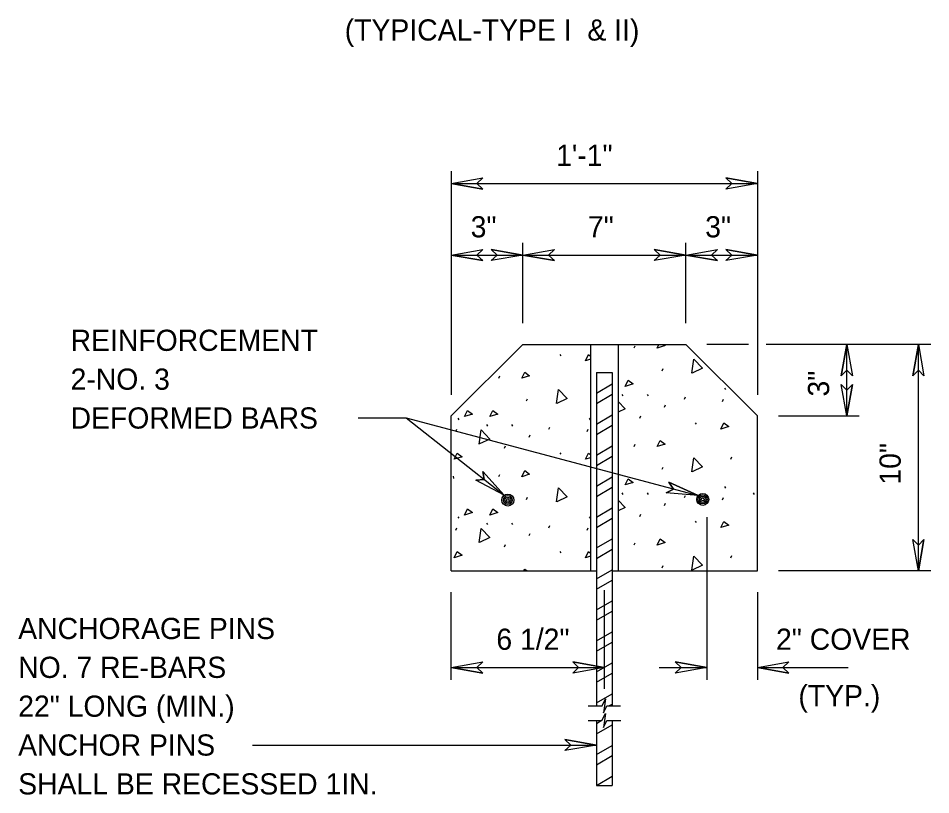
# Model space of a CAD drawing. Extents: x 12.4 to 19.6, y 6 to 16.2.
# Drawn here: x 16.834 to 19.416, y 11.739 to 13.937 of the extents above; entities that cross this region are included whole.
import ezdxf

# ---------------------------------------------------------------- set-up
doc = ezdxf.new("R2010")
doc.units = 0
for name, color, linetype in [('DETL-DIMS', 7, 'Continuous'), ('DETL-LINE', 7, 'Continuous'), ('DETL-NOTE', 7, 'Continuous'), ('DETL-PATT', 7, 'Continuous')]:
    doc.layers.add(name, color=color, linetype=linetype)

msp = doc.modelspace()

# ---------------------------------------------------------------- linework, layer by layer
at = {"layer": 'DETL-DIMS'}
for p, q in [((18.0593, 13.5044), (18.0593, 12.8713)), ((18.9255, 13.5044), (18.9255, 12.8713)), ((18.0593, 13.4694), (18.1486, 13.4851)), ((18.1318, 13.4694), (18.1486, 13.4851)), ((18.9255, 13.4694), (18.8361, 13.4851)), ((18.8361, 13.4851), (18.853, 13.4694)), ((18.0593, 13.4694), (18.9255, 13.4694)), ((18.0593, 13.4694), (18.1486, 13.4536)), ((18.1486, 13.4536), (18.1318, 13.4694)), ((18.9255, 13.4694), (18.8361, 13.4536)), ((18.853, 13.4694), (18.8361, 13.4536)), ((18.2618, 13.0738), (18.2618, 13.3019)), ((18.723, 13.0738), (18.723, 13.3019)), ((18.0593, 13.2669), (18.1486, 13.2826)), ((18.1318, 13.2669), (18.1486, 13.2826)), ((18.2618, 13.2669), (18.1724, 13.2826)), ((18.1724, 13.2826), (18.1893, 13.2669)), ((18.2618, 13.2669), (18.3511, 13.2826)), ((18.3343, 13.2669), (18.3511, 13.2826)), ((18.723, 13.2669), (18.6336, 13.2826)), ((18.6336, 13.2826), (18.6505, 13.2669)), ((18.723, 13.2669), (18.8124, 13.2826)), ((18.7955, 13.2669), (18.8124, 13.2826)), ((18.9255, 13.2669), (18.8361, 13.2826)), ((18.8361, 13.2826), (18.853, 13.2669)), ((18.0593, 13.2669), (18.2618, 13.2669)), ((18.0593, 13.2669), (18.1486, 13.2511)), ((18.1486, 13.2511), (18.1318, 13.2669)), ((18.2618, 13.2669), (18.1724, 13.2511)), ((18.1893, 13.2669), (18.1724, 13.2511)), ((18.2618, 13.2669), (18.723, 13.2669)), ((18.2618, 13.2669), (18.3511, 13.2511)), ((18.3511, 13.2511), (18.3343, 13.2669)), ((18.723, 13.2669), (18.6336, 13.2511)), ((18.6505, 13.2669), (18.6336, 13.2511)), ((18.723, 13.2669), (18.9255, 13.2669)), ((18.723, 13.2669), (18.8124, 13.2511)), ((18.8124, 13.2511), (18.7955, 13.2669)), ((18.9255, 13.2669), (18.8361, 13.2511)), ((18.853, 13.2669), (18.8361, 13.2511)), ((18.9005, 13.0138), (18.783, 13.0138)), ((19.4161, 13.0138), (18.9505, 13.0138)), ((19.1786, 13.0138), (19.1629, 12.9244)), ((19.1786, 12.8113), (19.1786, 13.0138)), ((19.1786, 13.0138), (19.1944, 12.9244)), ((19.3811, 13.0138), (19.3654, 12.9244)), ((19.3811, 12.3725), (19.3811, 13.0138)), ((19.3811, 13.0138), (19.3969, 12.9244)), ((19.1629, 12.9244), (19.1786, 12.9413)), ((19.1786, 12.9413), (19.1944, 12.9244)), ((19.3654, 12.9244), (19.3811, 12.9413)), ((19.3811, 12.9413), (19.3969, 12.9244)), ((19.1786, 12.8113), (19.1629, 12.9006)), ((19.1786, 12.8838), (19.1629, 12.9006)), ((19.1786, 12.8113), (19.1944, 12.9006)), ((19.1944, 12.9006), (19.1786, 12.8838)), ((18.9855, 12.8113), (19.2136, 12.8113)), ((17.796, 12.8055), (17.9316, 12.8055)), ((17.9316, 12.8055), (18.2094, 12.5866)), ((17.9316, 12.8055), (18.7579, 12.5858)), ((18.2094, 12.5866), (18.1489, 12.6544)), ((18.1489, 12.6544), (18.1524, 12.6315)), ((18.1524, 12.6315), (18.1294, 12.6296)), ((18.2094, 12.5866), (18.1294, 12.6296)), ((18.6878, 12.6044), (18.6675, 12.5935)), ((18.7579, 12.5858), (18.6755, 12.624)), ((18.6755, 12.624), (18.6878, 12.6044)), ((18.7579, 12.5858), (18.6675, 12.5935)), ((18.7824, 12.5249), (18.7824, 12.0641)), ((19.3811, 12.3725), (19.3654, 12.4619)), ((19.3811, 12.445), (19.3654, 12.4619)), ((19.3811, 12.3725), (19.3969, 12.4619)), ((19.3969, 12.4619), (19.3811, 12.445)), ((19.4161, 12.3725), (18.9855, 12.3725)), ((18.4924, 12.3175), (18.4924, 12.0383)), ((18.0593, 12.0641), (18.0593, 12.3125)), ((18.9255, 12.3125), (18.9255, 12.0641)), ((18.0593, 12.0991), (18.1486, 12.1149)), ((18.1318, 12.0991), (18.1486, 12.1149)), ((18.4924, 12.0991), (18.403, 12.1149)), ((18.403, 12.1149), (18.4199, 12.0991)), ((18.7824, 12.0991), (18.693, 12.1149)), ((18.693, 12.1149), (18.7099, 12.0991)), ((18.9255, 12.0991), (19.0149, 12.1149)), ((18.998, 12.0991), (19.0149, 12.1149)), ((18.0593, 12.0991), (18.4924, 12.0991)), ((18.0593, 12.0991), (18.1486, 12.0834)), ((18.1486, 12.0834), (18.1318, 12.0991)), ((18.4924, 12.0991), (18.403, 12.0834)), ((18.4199, 12.0991), (18.403, 12.0834)), ((18.6474, 12.0991), (18.7824, 12.0991)), ((18.7824, 12.0991), (18.693, 12.0834)), ((18.7099, 12.0991), (18.693, 12.0834)), ((18.9255, 12.0991), (19.1828, 12.0991)), ((18.9255, 12.0991), (19.0149, 12.0834)), ((19.0149, 12.0834), (18.998, 12.0991)), ((17.4969, 11.8795), (18.4699, 11.8795)), ((18.4699, 11.8795), (18.3805, 11.8953)), ((18.3805, 11.8953), (18.3974, 11.8795)), ((18.4699, 11.8795), (18.3805, 11.8638)), ((18.3974, 11.8795), (18.3805, 11.8638))]:
    msp.add_line(p, q, dxfattribs=at)
for points in [[(18.1486, 13.4536), (18.0593, 13.4694), (18.1486, 13.4851), (18.1318, 13.4694)], [(18.8361, 13.4851), (18.9255, 13.4694), (18.8361, 13.4536), (18.853, 13.4694)], [(18.1486, 13.2511), (18.0593, 13.2669), (18.1486, 13.2826), (18.1318, 13.2669)], [(18.1724, 13.2826), (18.2618, 13.2669), (18.1724, 13.2511), (18.1893, 13.2669)], [(18.3511, 13.2511), (18.2618, 13.2669), (18.3511, 13.2826), (18.3343, 13.2669)], [(18.6336, 13.2826), (18.723, 13.2669), (18.6336, 13.2511), (18.6505, 13.2669)], [(18.8124, 13.2511), (18.723, 13.2669), (18.8124, 13.2826), (18.7955, 13.2669)], [(18.8361, 13.2826), (18.9255, 13.2669), (18.8361, 13.2511), (18.853, 13.2669)], [(19.1629, 12.9244), (19.1786, 13.0138), (19.1944, 12.9244), (19.1786, 12.9413)], [(19.3654, 12.9244), (19.3811, 13.0138), (19.3969, 12.9244), (19.3811, 12.9413)], [(19.1944, 12.9006), (19.1786, 12.8113), (19.1629, 12.9006), (19.1786, 12.8838)], [(18.1489, 12.6544), (18.2094, 12.5866), (18.1294, 12.6296), (18.1524, 12.6315)], [(18.6755, 12.624), (18.7579, 12.5858), (18.6675, 12.5935), (18.6878, 12.6044)], [(19.3969, 12.4619), (19.3811, 12.3725), (19.3654, 12.4619), (19.3811, 12.445)], [(18.1486, 12.0834), (18.0593, 12.0991), (18.1486, 12.1149), (18.1318, 12.0991)], [(18.403, 12.1149), (18.4924, 12.0991), (18.403, 12.0834), (18.4199, 12.0991)], [(18.693, 12.1149), (18.7824, 12.0991), (18.693, 12.0834), (18.7099, 12.0991)], [(19.0149, 12.0834), (18.9255, 12.0991), (19.0149, 12.1149), (18.998, 12.0991)], [(18.3805, 11.8953), (18.4699, 11.8795), (18.3805, 11.8638), (18.3974, 11.8795)]]:
    msp.add_lwpolyline(points, close=True, dxfattribs=at)
at = {"layer": 'DETL-LINE'}
for p, q in [((18.0593, 12.8113), (18.2618, 13.0138)), ((18.2618, 13.0138), (18.723, 13.0138)), ((18.453, 13.0138), (18.453, 12.3725)), ((18.5318, 13.0138), (18.5318, 12.3725)), ((18.723, 13.0138), (18.9255, 12.8113)), ((18.4699, 12.9343), (18.4699, 11.99)), ((18.4699, 12.9343), (18.5149, 12.9343)), ((18.5149, 12.9343), (18.5149, 11.99)), ((18.0593, 12.3725), (18.0593, 12.8113)), ((18.9255, 12.3725), (18.9255, 12.8113)), ((18.0593, 12.3725), (18.4699, 12.3725)), ((18.5149, 12.3725), (18.9255, 12.3725)), ((18.4465, 11.99), (18.486, 11.99)), ((18.4999, 11.99), (18.5381, 11.99)), ((18.447, 11.9485), (18.4855, 11.9485)), ((18.4699, 11.9485), (18.4699, 11.765)), ((18.4994, 11.9485), (18.5388, 11.9485)), ((18.5149, 11.9485), (18.5149, 11.765)), ((18.4699, 11.765), (18.5149, 11.765))]:
    msp.add_line(p, q, dxfattribs=at)
for points in [[(18.486, 11.99), (18.496, 12.0106), (18.4906, 11.9704), (18.4999, 11.99)], [(18.4855, 11.9485), (18.4955, 11.969), (18.4901, 11.9289), (18.4994, 11.9485)]]:
    msp.add_lwpolyline(points, dxfattribs=at)
for centre, radius in [((18.2195, 12.573), 0.0169), ((18.2195, 12.573), 0.0127), ((18.2195, 12.573), 0.00844), ((18.2195, 12.573), 0.00422), ((18.7709, 12.575), 0.0169), ((18.7709, 12.575), 0.0127), ((18.7709, 12.575), 0.00844), ((18.7709, 12.575), 0.00422)]:
    msp.add_circle(centre, radius, dxfattribs=at)
at = {"layer": 'DETL-PATT'}
for p, q in [((18.5771, 13.004), (18.5799, 13.0102)), ((18.3663, 12.9857), (18.3691, 12.9815)), ((18.6559, 12.9393), (18.6587, 12.9455)), ((18.1939, 12.9186), (18.1966, 12.9248)), ((18.4699, 12.8758), (18.5149, 12.9018)), ((18.8325, 12.89), (18.8353, 12.8859)), ((18.2726, 12.8539), (18.2754, 12.8601)), ((18.4699, 12.8465), (18.5149, 12.8725)), ((18.5421, 12.8724), (18.5449, 12.8682)), ((18.6135, 12.8724), (18.6162, 12.8682)), ((18.719, 12.8588), (18.7218, 12.865)), ((18.8272, 12.8526), (18.83, 12.8588)), ((18.6628, 12.8366), (18.6656, 12.8428)), ((18.4699, 12.788), (18.5149, 12.8141)), ((18.5934, 12.8053), (18.5961, 12.8116)), ((18.0779, 12.8046), (18.0807, 12.8005)), ((18.1589, 12.787), (18.1616, 12.7828)), ((18.2302, 12.787), (18.233, 12.7828)), ((18.4493, 12.8046), (18.452, 12.8005)), ((18.4699, 12.7588), (18.5149, 12.7849)), ((18.7495, 12.7922), (18.7523, 12.788)), ((18.0727, 12.7672), (18.0754, 12.7734)), ((18.2796, 12.7512), (18.2824, 12.7574)), ((18.3358, 12.7734), (18.3386, 12.7796)), ((18.444, 12.7672), (18.4468, 12.7734)), ((18.5771, 12.7251), (18.5799, 12.7313)), ((18.2101, 12.7199), (18.2129, 12.7262)), ((18.3663, 12.7068), (18.3691, 12.7026)), ((18.4699, 12.7004), (18.5149, 12.7264)), ((18.4699, 12.6711), (18.5149, 12.6971)), ((18.8504, 12.6888), (18.8532, 12.6951)), ((18.6559, 12.6604), (18.6587, 12.6666)), ((18.0651, 12.6403), (18.0658, 12.634)), ((18.1939, 12.6397), (18.1966, 12.6459)), ((18.4699, 12.6128), (18.5149, 12.6386)), ((18.4699, 12.5835), (18.5149, 12.6095)), ((18.8325, 12.6112), (18.8353, 12.607)), ((18.2726, 12.575), (18.2754, 12.5812)), ((18.5421, 12.5935), (18.5449, 12.5893)), ((18.6135, 12.5935), (18.6162, 12.5893)), ((18.719, 12.5799), (18.7218, 12.5862)), ((18.8272, 12.5737), (18.83, 12.5799)), ((18.9135, 12.5935), (18.9162, 12.5893)), ((18.4699, 12.525), (18.5149, 12.551)), ((18.6628, 12.5577), (18.6656, 12.564)), ((18.0779, 12.5258), (18.0807, 12.5216)), ((18.4493, 12.5258), (18.452, 12.5216)), ((18.5934, 12.5265), (18.5961, 12.5327)), ((18.1589, 12.5081), (18.1616, 12.5039)), ((18.2302, 12.5081), (18.233, 12.5039)), ((18.3358, 12.4945), (18.3386, 12.5008)), ((18.4699, 12.4958), (18.5149, 12.5218)), ((18.7495, 12.5133), (18.7523, 12.5092)), ((18.0727, 12.4883), (18.0754, 12.4945)), ((18.2796, 12.4723), (18.2824, 12.4786)), ((18.444, 12.4883), (18.4468, 12.4945)), ((18.2101, 12.4411), (18.2129, 12.4473)), ((18.4699, 12.4374), (18.5149, 12.4633)), ((18.5771, 12.4462), (18.5799, 12.4524)), ((18.3663, 12.4279), (18.3691, 12.4238)), ((18.4699, 12.4081), (18.5149, 12.4341)), ((18.8504, 12.4099), (18.8532, 12.4162)), ((18.4699, 12.3496), (18.5149, 12.3756)), ((18.6559, 12.3815), (18.6587, 12.3878)), ((18.4699, 12.3204), (18.5149, 12.3464)), ((18.4699, 12.262), (18.5149, 12.2879)), ((18.4699, 12.2328), (18.5149, 12.2586)), ((18.4699, 12.1743), (18.5149, 12.2003)), ((18.4699, 12.145), (18.5149, 12.171)), ((18.4699, 12.0866), (18.5149, 12.1126)), ((18.4699, 12.0574), (18.5149, 12.0834)), ((18.4699, 11.9989), (18.5149, 12.0249)), ((18.5053, 11.99), (18.5149, 11.9956)), ((18.4699, 11.9405), (18.4839, 11.9485)), ((18.4699, 11.9113), (18.5149, 11.9371)), ((18.4699, 11.8528), (18.5149, 11.8786)), ((18.4699, 11.8235), (18.5149, 11.8495)), ((18.4699, 11.765), (18.5149, 11.791))]:
    msp.add_line(p, q, dxfattribs=at)
for points in [[(18.6421, 13.0035), (18.6471, 13.0138)], [(18.6599, 13.0138), (18.6643, 13.0104), (18.6421, 13.0035)], [(18.4392, 12.9677), (18.4475, 12.985), (18.453, 12.9808)], [(18.453, 12.972), (18.4392, 12.9677)], [(18.7403, 12.9321), (18.7458, 12.9718), (18.7706, 12.9461), (18.7409, 12.9323)], [(18.2589, 12.9181), (18.2672, 12.9354), (18.2811, 12.925), (18.2589, 12.9181)], [(18.5518, 12.8949), (18.5601, 12.9122), (18.574, 12.9018), (18.5518, 12.8949)], [(18.3571, 12.8467), (18.3626, 12.8864), (18.3874, 12.8607), (18.3577, 12.8469)], [(18.5318, 12.8519), (18.5518, 12.8312), (18.5318, 12.8219)], [(18.0972, 12.8095), (18.1056, 12.8268), (18.1194, 12.8164), (18.0972, 12.8095)], [(18.1686, 12.8095), (18.1769, 12.8268), (18.1908, 12.8164), (18.1686, 12.8095)], [(18.8224, 12.7742), (18.8307, 12.7915), (18.8446, 12.7811), (18.8224, 12.7742)], [(18.1382, 12.7318), (18.1437, 12.7715), (18.1686, 12.7458), (18.1389, 12.7321)], [(18.6421, 12.7246), (18.6505, 12.7419), (18.6643, 12.7315), (18.6421, 12.7246)], [(18.0678, 12.6888), (18.0761, 12.7061), (18.09, 12.6957), (18.0678, 12.6888)], [(18.4392, 12.6888), (18.4475, 12.7061), (18.453, 12.702)], [(18.453, 12.6931), (18.4392, 12.6888)], [(18.7403, 12.6532), (18.7458, 12.6929), (18.7706, 12.6672), (18.7409, 12.6535)], [(18.2589, 12.6392), (18.2672, 12.6565), (18.2811, 12.6461), (18.2589, 12.6392)], [(18.5518, 12.616), (18.5601, 12.6333), (18.574, 12.6229), (18.5518, 12.616)], [(18.3571, 12.5678), (18.3626, 12.6075), (18.3874, 12.5818), (18.3577, 12.5681)], [(18.0972, 12.5306), (18.1056, 12.5479), (18.1194, 12.5375), (18.0972, 12.5306)], [(18.1686, 12.5306), (18.1769, 12.5479), (18.1908, 12.5375), (18.1686, 12.5306)], [(18.5318, 12.573), (18.5518, 12.5523), (18.5318, 12.543)], [(18.8224, 12.4953), (18.8307, 12.5126), (18.8446, 12.5022), (18.8224, 12.4953)], [(18.1382, 12.4529), (18.1437, 12.4926), (18.1686, 12.4669), (18.1389, 12.4532)], [(18.6421, 12.4457), (18.6505, 12.463), (18.6643, 12.4526), (18.6421, 12.4457)], [(18.0678, 12.4099), (18.0761, 12.4272), (18.09, 12.4168), (18.0678, 12.4099)], [(18.4392, 12.4099), (18.4475, 12.4272), (18.453, 12.4231)], [(18.453, 12.4142), (18.4392, 12.4099)], [(18.7403, 12.3743), (18.7458, 12.414), (18.7706, 12.3883), (18.7409, 12.3746)], [(18.2648, 12.3725), (18.2672, 12.3776), (18.274, 12.3725)]]:
    msp.add_lwpolyline(points, dxfattribs=at)

# ---------------------------------------------------------------- texts
at = {"layer": 'DETL-NOTE'}
for s, p in [('(TYPICAL-TYPE I  & II)', (17.758, 13.8742)), ('1\'-1"', (18.3561, 13.5194)), ('3"', (18.1143, 13.3169)), ('7"', (18.4461, 13.3169)), ('3"', (18.7779, 13.3169)), ('REINFORCEMENT', (16.9823, 12.9955)), ('2-NO. 3', (16.9823, 12.8855)), ('DEFORMED BARS', (16.9823, 12.7755)), ('ANCHORAGE PINS', (16.8341, 12.1795)), ('6 1/2"', (18.1871, 12.1491)), ('2" COVER', (18.9783, 12.1491)), ('NO. 7 RE-BARS', (16.8341, 12.0695)), ('(TYP.)', (19.0416, 11.9891)), ('22" LONG (MIN.)', (16.8341, 11.9595)), ('ANCHOR PINS', (16.8341, 11.8495)), ('SHALL BE RECESSED 1IN.', (16.8341, 11.7395))]:
    msp.add_text(s, height=0.06, dxfattribs=at).set_placement(p)
for s, p in [('3"', (19.1286, 12.8663)), ('10"', (19.3311, 12.6169))]:
    msp.add_text(s, height=0.06, rotation=90, dxfattribs=at).set_placement(p)

doc.saveas('drawing.dxf')
